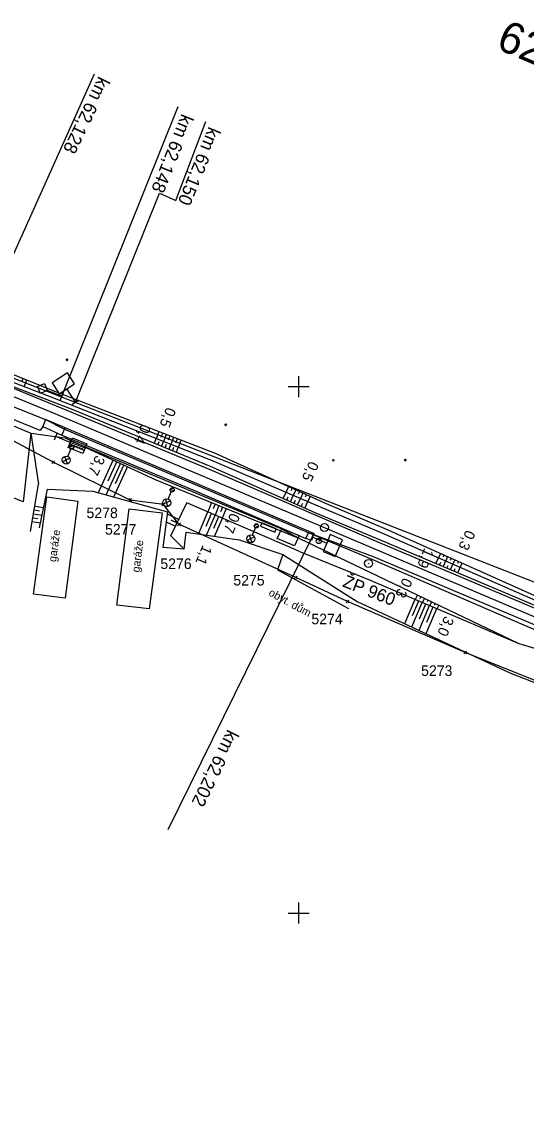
# Model space of a CAD drawing. Extents: x -805636 to -804553, y -1165340 to -1164656.
# Drawn here: x -805352.6 to -805256.7, y -1165035.6 to -1164830.7 of the extents above; entities that cross this region are included whole.
import ezdxf

# ---------------------------------------------------------------- set-up
doc = ezdxf.new("R2010")
doc.units = 0
for name, color, linetype in [('0381KM061-064P - Vrstva 1', 7, 'Continuous'), ('0381KM061-064P - Vrstva 13', 7, 'Continuous'), ('0381KM061-064P - Vrstva 14', 7, 'Continuous'), ('0381KM061-064P - Vrstva 16', 7, 'Continuous'), ('0381KM061-064P - Vrstva 17', 7, 'Continuous'), ('0381KM061-064P - Vrstva 23', 7, 'Continuous'), ('0381KM061-064P - Vrstva 25', 7, 'Continuous'), ('0381KM061-064P - Vrstva 4', 7, 'Continuous'), ('0381KM061-064P - Vrstva 48', 7, 'Continuous'), ('0381KM061-064P - Vrstva 49', 7, 'Continuous'), ('0381KM061-064P - Vrstva 7', 7, 'Continuous'), ('0381KM061-064P - Vrstva 8', 7, 'Continuous'), ('krizky_1000 - Vrstva 1', 7, 'Continuous'), ('szdc - hran DP', 7, 'Continuous'), ('szdc - szdc_cislo', 7, 'Continuous'), ('szdc - szdc_krizek', 7, 'Continuous'), ('vyt_sit - stávající', 7, 'Continuous')]:
    doc.layers.add(name, color=color, linetype=linetype)

msp = doc.modelspace()

# ---------------------------------------------------------------- linework, layer by layer
at = {"layer": '0381KM061-064P - Vrstva 1'}
for points in [[(-805362.07, -1164898.64), (-805347.39, -1164904.64), (-805344.65, -1164905.78)], [(-805344.65, -1164905.78), (-805313.66, -1164918.88), (-805286.17, -1164930.55), (-805256.63, -1164943.09), (-805230.48, -1164954.2), (-805205.12, -1164965.01), (-805202.66, -1164966.06)]]:
    msp.add_lwpolyline(points, dxfattribs=at)
at = {"layer": '0381KM061-064P - Vrstva 13'}
msp.add_lwpolyline([(-805321.75, -1164930.89), (-805321.36, -1164927.66), (-805311.3, -1164929.13), (-805302.99, -1164931.92), (-805304.04, -1164934.8)], dxfattribs=at)
at = {"layer": '0381KM061-064P - Vrstva 14'}
for points in [[(-805348.61, -1164907.57), (-805344.97, -1164909.22), (-805344.37, -1164907.83), (-805348.12, -1164906.22)], [(-805298.03, -1164927.49), (-805318.81, -1164918.63), (-805344.37, -1164907.83)], [(-805344.97, -1164909.22), (-805319.37, -1164919.91), (-805298.61, -1164928.83), (-805298.03, -1164927.49)], [(-805298.03, -1164927.49), (-805297.09, -1164927.83), (-805297.56, -1164929.24), (-805298.61, -1164928.83)]]:
    msp.add_lwpolyline(points, dxfattribs=at)
at = {"layer": '0381KM061-064P - Vrstva 16'}
msp.add_lwpolyline([(-805366.38, -1164898.98), (-805348.12, -1164906.22), (-805348.61, -1164907.57), (-805349.09, -1164908.36), (-805367.46, -1164900.88), (-805366.38, -1164898.98)], dxfattribs=at)
at = {"layer": '0381KM061-064P - Vrstva 17'}
for points in [[(-805369.75, -1164914.7), (-805368.04, -1164901.63), (-805350.89, -1164908.84), (-805352.32, -1164921.91), (-805369.75, -1164914.7)], [(-805344.45, -1164909.76), (-805340.69, -1164911.4), (-805303.48, -1164926.91), (-805299.84, -1164928.84)]]:
    msp.add_lwpolyline(points, dxfattribs=at)
at = {"layer": '0381KM061-064P - Vrstva 23'}
for points in [[(-805344.35, -1164940.19), (-805350.35, -1164939.42), (-805347.83, -1164920.92), (-805341.94, -1164921.79), (-805344.35, -1164940.19)], [(-805334.52, -1164941.49), (-805332.2, -1164923.19), (-805325.94, -1164923.98), (-805328.43, -1164942.24), (-805334.52, -1164941.49)], [(-805304.04, -1164934.8), (-805290.52, -1164942.17)]]:
    msp.add_lwpolyline(points, dxfattribs=at)
for points in [[(-805304.5, -1164927.66), (-805304.24, -1164927.04), (-805306.99, -1164925.86), (-805307.26, -1164926.49)], [(-805300.76, -1164930.22), (-805304.05, -1164928.83), (-805303.22, -1164926.92), (-805299.93, -1164928.3)]]:
    msp.add_lwpolyline(points, close=True, dxfattribs=at)
at = {"layer": '0381KM061-064P - Vrstva 25'}
for p, q in [((-805343.87, -1164913.27), (-805343.29, -1164911.89)), ((-805342.87, -1164911.22), (-805343.53, -1164911.49)), ((-805342.74, -1164911.6), (-805343.35, -1164911.85)), ((-805343.5, -1164913.62), (-805344.84, -1164914.27)), ((-805343.92, -1164914.67), (-805344.41, -1164913.26)), ((-805324.77, -1164921.36), (-805324.19, -1164919.98)), ((-805323.78, -1164919.31), (-805324.43, -1164919.58)), ((-805323.65, -1164919.69), (-805324.26, -1164919.94)), ((-805324.4, -1164921.71), (-805325.74, -1164922.36)), ((-805324.83, -1164922.76), (-805325.31, -1164921.34)), ((-805308.78, -1164928.2), (-805308.19, -1164926.82)), ((-805307.78, -1164926.15), (-805308.43, -1164926.42)), ((-805307.64, -1164926.53), (-805308.26, -1164926.78)), ((-805308.41, -1164928.55), (-805309.75, -1164929.2)), ((-805308.83, -1164929.6), (-805309.31, -1164928.19))]:
    msp.add_line(p, q, dxfattribs=at)
for centre, radius in [((-805343.13, -1164911.52), 0.4), ((-805343.13, -1164911.52), 0.4), ((-805344.16, -1164913.96), 0.749), ((-805324.03, -1164919.61), 0.4), ((-805324.03, -1164919.61), 0.4), ((-805325.06, -1164922.05), 0.749), ((-805308.03, -1164926.45), 0.4), ((-805308.03, -1164926.45), 0.4), ((-805309.07, -1164928.89), 0.749)]:
    msp.add_circle(centre, radius, dxfattribs=at)
at = {"layer": '0381KM061-064P - Vrstva 4'}
for points in [[(-805364.7, -1164895.97), (-805343.19, -1164904.86), (-805317.03, -1164915.68), (-805296.75, -1164924.42), (-805284.83, -1164929.56), (-805254.7, -1164942.26), (-805226.16, -1164954.55), (-805203.52, -1164964.18), (-805187.57, -1164970.92)], [(-805364.7, -1164895.97), (-805342.91, -1164904.36), (-805316.81, -1164915.12), (-805296.46, -1164924.13), (-805284.52, -1164929.13), (-805254.45, -1164941.83), (-805225.92, -1164953.93), (-805203.38, -1164963.47), (-805187.4, -1164970.45)], [(-805348.12, -1164906.22), (-805344.46, -1164908.09), (-805318.48, -1164919.08), (-805298.17, -1164927.71), (-805286.08, -1164932.79)], [(-805298.17, -1164927.71), (-805285.87, -1164932.24)], [(-805286.08, -1164932.79), (-805257.4, -1164945.18)], [(-805285.87, -1164932.24), (-805257.21, -1164944.39)], [(-805257.4, -1164945.18), (-805227.5, -1164957.9), (-805205.55, -1164967.2), (-805161.7, -1164987.26), (-805121.4, -1165011.84), (-805082.08, -1165035.58)], [(-805257.21, -1164944.39), (-805227.21, -1164957.06), (-805205.17, -1164966.48), (-805161.59, -1164986.72), (-805120.84, -1165010.88), (-805082.03, -1165034.98)]]:
    msp.add_lwpolyline(points, dxfattribs=at)
at = {"layer": '0381KM061-064P - Vrstva 48'}
for p, q in [((-805352.38, -1164898.48), (-805352.62, -1164899.09)), ((-805351.69, -1164898.76), (-805352.17, -1164899.97)), ((-805327.03, -1164909.84), (-805326.53, -1164908.55)), ((-805327.08, -1164909.82), (-805327.46, -1164910.73)), ((-805326.54, -1164910.46), (-805326.77, -1164911.02)), ((-805326.13, -1164909.59), (-805325.83, -1164908.82)), ((-805325.69, -1164910.37), (-805326.07, -1164911.3)), ((-805325.63, -1164910.39), (-805325.13, -1164909.09)), ((-805324.73, -1164910.14), (-805324.43, -1164909.36)), ((-805324.24, -1164910.94), (-805323.73, -1164909.62)), ((-805323.34, -1164910.68), (-805323.04, -1164909.89)), ((-805322.84, -1164911.49), (-805322.34, -1164910.16)), ((-805325.14, -1164911.02), (-805325.38, -1164911.59)), ((-805324.29, -1164910.92), (-805324.69, -1164911.88)), ((-805323.75, -1164911.58), (-805323.99, -1164912.16)), ((-805322.9, -1164911.47), (-805323.3, -1164912.45)), ((-805338.05, -1164920.13), (-805335.23, -1164913.99)), ((-805336.59, -1164920.54), (-805333.87, -1164914.62)), ((-805336.21, -1164917.92), (-805334.55, -1164914.3)), ((-805335.12, -1164920.94), (-805332.51, -1164915.25)), ((-805334.79, -1164918.42), (-805333.19, -1164914.93)), ((-805302.93, -1164921.26), (-805302.4, -1164920.06)), ((-805301.91, -1164918.97), (-805302.4, -1164920.06)), ((-805301.56, -1164921.87), (-805301.02, -1164920.66)), ((-805301.23, -1164919.28), (-805301.47, -1164919.82)), ((-805300.54, -1164919.59), (-805301.03, -1164920.66)), ((-805299.86, -1164919.9), (-805300.1, -1164920.43)), ((-805299.18, -1164920.21), (-805299.65, -1164921.25)), ((-805298.49, -1164920.52), (-805298.73, -1164921.03)), ((-805297.81, -1164920.83), (-805298.27, -1164921.85)), ((-805348.46, -1164923.02), (-805350.15, -1164922.74)), ((-805316.54, -1164922.03), (-805317.26, -1164923.8)), ((-805315.84, -1164922.32), (-805316.21, -1164923.21)), ((-805315.15, -1164922.6), (-805315.88, -1164924.4)), ((-805314.45, -1164922.88), (-805314.82, -1164923.79)), ((-805302.24, -1164921.57), (-805301.98, -1164920.96)), ((-805300.87, -1164922.17), (-805300.6, -1164921.56)), ((-805300.19, -1164922.48), (-805299.64, -1164921.25)), ((-805299.5, -1164922.78), (-805299.23, -1164922.17)), ((-805298.81, -1164923.08), (-805298.27, -1164921.85)), ((-805349.55, -1164925.11), (-805350.5, -1164924.96)), ((-805348.76, -1164924.48), (-805350.38, -1164924.22)), ((-805349.27, -1164923.64), (-805350.26, -1164923.48)), ((-805324.95, -1164924.17), (-805322.77, -1164925.24)), ((-805319.05, -1164928), (-805317.25, -1164923.81)), ((-805317.59, -1164926.51), (-805316.56, -1164924.1)), ((-805317.51, -1164928.22), (-805315.87, -1164924.4)), ((-805316.12, -1164926.88), (-805315.18, -1164924.7)), ((-805315.97, -1164928.45), (-805314.49, -1164924.99)), ((-805313.76, -1164923.17), (-805314.5, -1164924.99)), ((-805349.06, -1164925.95), (-805350.62, -1164925.69)), ((-805325.14, -1164925.67), (-805323.4, -1164926.53)), ((-805324.26, -1164925.3), (-805323.09, -1164925.89)), ((-805273.91, -1164933.61), (-805273.44, -1164932.5)), ((-805273.06, -1164931.69), (-805273.43, -1164932.51)), ((-805272.38, -1164932), (-805272.56, -1164932.4)), ((-805272.52, -1164934.2), (-805272.06, -1164933.1)), ((-805271.7, -1164932.3), (-805272.05, -1164933.11)), ((-805271.01, -1164932.61), (-805271.19, -1164933.01)), ((-805270.33, -1164932.92), (-805270.68, -1164933.71)), ((-805273.21, -1164933.9), (-805272.98, -1164933.35)), ((-805271.83, -1164934.49), (-805271.6, -1164933.95)), ((-805271.14, -1164934.78), (-805270.69, -1164933.7)), ((-805270.45, -1164935.07), (-805270.23, -1164934.54)), ((-805269.64, -1164933.23), (-805269.82, -1164933.62)), ((-805269.76, -1164935.36), (-805269.31, -1164934.31)), ((-805268.96, -1164933.53), (-805269.31, -1164934.31)), ((-805279.84, -1164945.01), (-805277.88, -1164940.4)), ((-805278.48, -1164945.65), (-805276.5, -1164940.98)), ((-805278.37, -1164943.48), (-805277.19, -1164940.69)), ((-805277.44, -1164939.56), (-805277.85, -1164940.41)), ((-805277.01, -1164944.09), (-805275.81, -1164941.28)), ((-805276.76, -1164939.88), (-805276.96, -1164940.29)), ((-805276.09, -1164940.21), (-805276.46, -1164941)), ((-805275.41, -1164940.53), (-805275.59, -1164940.91)), ((-805274.73, -1164940.85), (-805275.08, -1164941.58)), ((-805274.06, -1164941.18), (-805274.22, -1164941.53)), ((-805277.12, -1164946.29), (-805275.12, -1164941.57)), ((-805275.77, -1164946.92), (-805273.74, -1164942.16)), ((-805275.64, -1164944.71), (-805274.43, -1164941.86)), ((-805273.38, -1164941.5), (-805273.7, -1164942.17))]:
    msp.add_line(p, q, dxfattribs=at)
at = {"layer": '0381KM061-064P - Vrstva 49'}
for p, q in [((-805343.83, -1164895.11), (-805344.18, -1164894.75)), ((-805343.83, -1164894.75), (-805344.18, -1164895.11)), ((-805313.7, -1164907.45), (-805314.05, -1164907.1)), ((-805313.7, -1164907.1), (-805314.05, -1164907.45)), ((-805293.23, -1164914.18), (-805293.58, -1164913.83)), ((-805293.23, -1164913.83), (-805293.58, -1164914.18)), ((-805279.54, -1164914.16), (-805279.9, -1164913.81)), ((-805279.54, -1164913.81), (-805279.9, -1164914.16))]:
    msp.add_line(p, q, dxfattribs=at)
for points in [[(-805364.02, -1164893.8), (-805346.07, -1164901.02), (-805315.87, -1164912.66), (-805295.19, -1164922.01)], [(-805366.61, -1164894.35), (-805364.7, -1164895.97), (-805342.91, -1164904.36), (-805316.81, -1164915.12), (-805296.46, -1164924.13)], [(-805364.49, -1164895.2), (-805347.1, -1164901.93), (-805316.44, -1164914.01), (-805295.94, -1164922.85)], [(-805350.89, -1164908.84), (-805349.46, -1164918.54)], [(-805350.89, -1164908.84), (-805344.45, -1164909.76), (-805327.24, -1164917.67), (-805299.84, -1164928.84), (-805258.14, -1164948.79)], [(-805350.92, -1164927.51), (-805349.46, -1164918.54)], [(-805349.24, -1164926.82), (-805347.72, -1164919.48), (-805339.1, -1164919.84), (-805324.89, -1164923.77)], [(-805321.75, -1164930.89), (-805324.29, -1164928.33), (-805321.22, -1164922.1)], [(-805299.97, -1164931.23), (-805321.22, -1164922.1)], [(-805295.94, -1164922.85), (-805284.04, -1164927.86), (-805253.46, -1164941.25), (-805223.68, -1164953.23)], [(-805295.19, -1164922.01), (-805283.65, -1164926.95), (-805253.5, -1164940.46), (-805223.68, -1164953.23)], [(-805324.89, -1164923.77), (-805325.79, -1164930.57)], [(-805296.46, -1164924.13), (-805284.52, -1164929.13), (-805254.45, -1164941.83), (-805225.92, -1164953.93)], [(-805321.75, -1164930.89), (-805321.36, -1164927.66), (-805311.3, -1164929.13), (-805302.99, -1164931.92)], [(-805321.75, -1164930.89), (-805325.79, -1164930.57)], [(-805302.99, -1164931.92), (-805288.85, -1164940.8), (-805259.86, -1164954.37)], [(-805299.97, -1164931.23), (-805286.39, -1164936.78), (-805258.14, -1164948.79)], [(-805258.14, -1164948.79), (-805227.5, -1164957.9)], [(-805259.86, -1164954.37), (-805233.78, -1164964.57)]]:
    msp.add_lwpolyline(points, dxfattribs=at)
at = {"layer": '0381KM061-064P - Vrstva 7'}
for p, q in [((-805343.05, -1164903.36), (-805341.79, -1164902.55)), ((-805297.43, -1164928.54), (-805324.84, -1164984.17)), ((-805297.14, -1164927.85), (-805297.72, -1164929.23)), ((-805296.2, -1164929.3), (-805296.11, -1164929.34))]:
    msp.add_line(p, q, dxfattribs=at)
for points in [[(-805342.42, -1164902.96), (-805326.45, -1164863.29), (-805323.31, -1164864.66), (-805317.63, -1164849.64)], [(-805342.42, -1164902.96), (-805344.04, -1164900.43), (-805342.56, -1164899.49), (-805343.91, -1164897.38), (-805346.86, -1164899.27), (-805345.51, -1164901.37), (-805344.04, -1164900.43)], [(-805297.43, -1164928.54), (-805294.67, -1164929.71), (-805295.35, -1164931.32), (-805293.05, -1164932.3), (-805291.68, -1164929.08), (-805293.98, -1164928.1), (-805294.67, -1164929.71)]]:
    msp.add_lwpolyline(points, dxfattribs=at)
for centre, radius in [((-805295.08, -1164926.77), 0.75), ((-805296.16, -1164929.32), 0.5)]:
    msp.add_circle(centre, radius, dxfattribs=at)
at = {"layer": '0381KM061-064P - Vrstva 8'}
for p, q in [((-805363.02, -1164894.54), (-805338.8, -1164840.62)), ((-805344.97, -1164901.83), (-805322.86, -1164846.82)), ((-805345.25, -1164902.52), (-805344.69, -1164901.13)), ((-805345.86, -1164908.78), (-805346.45, -1164910.16)), ((-805343.41, -1164911.01), (-805342.5, -1164910.64)), ((-805343.37, -1164910.58), (-805342.99, -1164910.43)), ((-805342.92, -1164911.21), (-805342.01, -1164910.84)), ((-805342.44, -1164911.42), (-805341.52, -1164911.05)), ((-805341.95, -1164911.63), (-805341.03, -1164911.26)), ((-805341.46, -1164911.83), (-805340.55, -1164911.46)), ((-805340.97, -1164912.04), (-805340.68, -1164911.92))]:
    msp.add_line(p, q, dxfattribs=at)
for points in [[(-805344.97, -1164901.83), (-805347.76, -1164900.72), (-805349.06, -1164901.28), (-805349.62, -1164899.98), (-805348.32, -1164899.42), (-805347.76, -1164900.72)], [(-805343.39, -1164910.63), (-805346.15, -1164909.47)], [(-805343, -1164909.72), (-805340.24, -1164910.88), (-805341.02, -1164912.73), (-805343.78, -1164911.56), (-805343, -1164909.72)]]:
    msp.add_lwpolyline(points, dxfattribs=at)
msp.add_lwpolyline([(-805343.26, -1164910.32), (-805340.49, -1164911.48), (-805340.76, -1164912.13), (-805343.53, -1164910.96)], close=True, dxfattribs=at)
at = {"layer": 'krizky_1000 - Vrstva 1'}
for points in [[(-805300, -1164898), (-805300, -1164902)], [(-805302, -1164900), (-805298, -1164900)], [(-805300, -1164998), (-805300, -1165002)], [(-805302, -1165000), (-805298, -1165000)]]:
    msp.add_lwpolyline(points, dxfattribs=at)
at = {"layer": 'szdc - hran DP'}
for p, q in [((-805367.78, -1164893.1), (-805249.75, -1164939.24)), ((-805346.65, -1164914.36), (-805367.9, -1164903.11)), ((-805332.02, -1164921.55), (-805346.65, -1164914.36)), ((-805325.7, -1164922.37), (-805332.02, -1164921.55)), ((-805322.74, -1164926.15), (-805325.7, -1164922.37)), ((-805300.55, -1164936.27), (-805322.74, -1164926.15)), ((-805290.72, -1164940.83), (-805300.55, -1164936.27)), ((-805268.35, -1164950.48), (-805290.72, -1164940.83)), ((-805235.86, -1164963.58), (-805268.35, -1164950.48))]:
    msp.add_line(p, q, dxfattribs=at)
at = {"layer": 'szdc - szdc_krizek'}
for p, q in [((-805346.39, -1164914.62), (-805346.92, -1164914.09)), ((-805346.92, -1164914.62), (-805346.39, -1164914.09)), ((-805331.76, -1164921.81), (-805332.29, -1164921.28)), ((-805332.29, -1164921.81), (-805331.76, -1164921.28)), ((-805325.44, -1164922.64), (-805325.97, -1164922.1)), ((-805325.97, -1164922.64), (-805325.44, -1164922.1)), ((-805322.47, -1164926.42), (-805323.01, -1164925.89)), ((-805323.01, -1164926.42), (-805322.47, -1164925.89)), ((-805300.29, -1164936.53), (-805300.82, -1164936.01)), ((-805300.82, -1164936.53), (-805300.29, -1164936.01)), ((-805290.46, -1164941.09), (-805290.99, -1164940.56)), ((-805290.99, -1164941.09), (-805290.46, -1164940.56)), ((-805268.08, -1164950.75), (-805268.62, -1164950.22)), ((-805268.62, -1164950.75), (-805268.08, -1164950.22))]:
    msp.add_line(p, q, dxfattribs=at)
at = {"layer": 'vyt_sit - stávající'}
msp.add_line((-805286.76, -1164933.55), (-805286.68, -1164933.61), dxfattribs=at)
msp.add_circle((-805286.72, -1164933.58), 0.756, dxfattribs=at)

# ---------------------------------------------------------------- texts
at = {"layer": '0381KM061-064P - Vrstva 23'}
for s, rotation, p in [('garáže', 82.2322, (-805346.1, -1164933.37)), ('garáže', 82.7783, (-805330.26, -1164935.34)), (' obyt. dům', 331.3934, (-805306.33, -1164939.31))]:
    msp.add_text(s, height=1.5, rotation=rotation, dxfattribs=at).set_placement(p)
at = {"layer": '0381KM061-064P - Vrstva 48'}
for s, rotation, p in [('0,5', 248.495, (-805325.1, -1164903.79)), ('0,4', 247.5875, (-805329.86, -1164906.99)), ('3,7', 245.3182, (-805338.51, -1164912.91)), ('0,5', 245.6505, (-805297.92, -1164914.02)), ('0,7', 247.8034, (-805312.93, -1164923.87)), ('0,3', 245.8554, (-805268.17, -1164927.09)), ('1,1', 246.7728, (-805318.19, -1164929.95)), ('1,9', 247.0941, (-805276.08, -1164930.53)), ('0,3', 244.4427, (-805280.1, -1164936.16)), ('3,0', 246.9723, (-805272.24, -1164943.45))]:
    msp.add_text(s, height=2, rotation=rotation, dxfattribs=at).set_placement(p)
at = {"layer": '0381KM061-064P - Vrstva 7'}
for s, height, rotation, p in [('62,2', 6, 337.0034, (-805262.71, -1164835.71)), ('km 62,150', 2.5, 247.6272, (-805317.06, -1164850.49)), ('km 62,202', 2.5, 243.7716, (-805313.5, -1164964.97))]:
    msp.add_text(s, height=height, rotation=rotation, dxfattribs=at).set_placement(p)
at = {"layer": '0381KM061-064P - Vrstva 8'}
for s, rotation, p in [('km 62,128', 244.0036, (-805337.99, -1164840.93)), ('km 62,148', 248.1034, (-805322.21, -1164848.06))]:
    msp.add_text(s, height=2.5, rotation=rotation, dxfattribs=at).set_placement(p)
at = {"layer": 'szdc - szdc_cislo'}
for s, p in [('5278', (-805340.31, -1164924.98)), ('5277', (-805336.79, -1164928.11)), ('5276', (-805326.28, -1164934.64)), ('5275', (-805312.41, -1164937.78)), ('5274', (-805297.58, -1164945.14)), ('5273', (-805276.73, -1164954.95))]:
    msp.add_text(s, height=2, dxfattribs=at).set_placement(p)
at = {"layer": 'vyt_sit - stávající'}
msp.add_text('ŽP 960', height=2.4, rotation=338.5611, dxfattribs=at).set_placement((-805291.82, -1164937.92))

doc.saveas('drawing.dxf')
